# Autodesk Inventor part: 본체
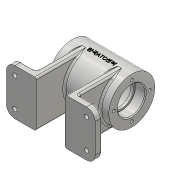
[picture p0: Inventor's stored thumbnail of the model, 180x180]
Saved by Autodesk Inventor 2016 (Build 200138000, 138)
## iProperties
Created: 2017-02
Part Number: 본체
Material: 알루미늄 6061
Document SubType Name: Modeling
Designer: H
Density: 2.7 g/cm^3
Appearance: 알루미늄 - 평지
Mass: 354.498 g
Surface Area: 423.593 cm^2
Volume: 131.296 cm^3
Author: H
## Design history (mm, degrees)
sketch "스케치1"
  geometry: L1 (0, 0)-(48.276, 0); L2 (0, 0)-(-37.135, 0); L3 (-35, 0)-(-35, 27); L4 (-35, 27)-(35, 27); L5 (35, 27)-(35, 0); L6 (0, 0)-(0, 35.697)
  constraints: 12 end point, 2 horizontal, 2 perpendicular, 2 point on line, 2 vertical
  dimensions: "d0" = 70 distance of L3.end L4.end; "d1" = 70 diameter of L3 L6; "d2" = 54 diameter of L4 L1
revolve "회전1" sketch "스케치1" stored, may be unused: angle "d3" = 90 deg
node "작업 평면1"
sketch "스케치2"
  geometry: L1 (35, 27)-(35, -27) reference; L2 (-35, 27)-(-35, -27) reference; L3 (0, 0)-(-50.692, 0); L4 (0, 0)-(76.762, 0); L5 (52, 27)-(-52, 27); L6 (-52, 27)-(-52, -27); L7 (-52, -27)-(52, -27); L8 (52, -27)-(52, 27); L9 (52, 27)-(-52, -27); L10 (-52, 27)-(52, -27)
  constraints: 16 end point, 3 horizontal, 2 midpoint, 2 parallel, 1 perpendicular
  dimensions: "d5" = 54 distance of L5.end L6.end; "d6" = 104 distance of L5.start L5.end
extrude "돌출1" join sketch "스케치2" distance "d7" = 8; taper "d8" = 0 deg
sketch "스케치3"
  geometry: L1 (0, 0)-(104, 0) reference; L2 (104, 0)-(104, 8) reference; L3 (0, 8)-(104, 8) reference; L4 (0, 0)-(0, 8) reference; L5 (52, 8)-(52, 0); L6 (69, 8)-(69, 0); L7 (35, 8)-(35, 0); L8 (35, 0)-(69, 0); L9 (35, 8)-(69, 8); 1 further point
  constraints: 10 end point, 2 midpoint, 2 perpendicular, 2 point on line, 2 symmetric about line, 1 collinear
  dimensions: "d9" = 17 distance from line of L6 L5.start
extrude "돌출2" cut sketch "스케치3" stored distance "d10" = 8; taper "d11" = 0 deg
sketch "스케치4"
  geometry: L1 (17, -27)-(17, 27) reference; L2 (52, 27)-(17, 27) reference; L3 (52, -27)-(52, 27) reference; L4 (17, -27)-(52, -27) reference; L5 (-17, 27)-(-17, -27) reference; L6 (-52, -27)-(-17, -27) reference; L7 (-52, 27)-(-52, -27) reference; L8 (-17, 27)-(-52, 27) reference; L9 (25, 27)-(25, -27); L10 (-25, 27)-(-25, -27); L11 (-25, 27)-(-17, 27); L12 (-17, 27)-(-17, -27); L13 (-17, -27)-(-25, -27); L14 (17, -27)-(25, -27); L15 (17, -27)-(17, 27); L16 (17, 27)-(25, 27); 1 further point
  constraints: 16 end point, 5 collinear, 4 point on line, 2 perpendicular, 1 vertical
  dimensions: "d12" = 8 distance between parallel lines of L9 L1; "d13" = 8 distance between parallel lines of L5 L10
extrude "돌출3" join sketch "스케치4" stored distance "d14" = 0; taper "d15" = 0 deg
fillet "모깎기1" dims "d16" = 10, "d17" = 10, "d18" = 10, "d19" = 10
sketch "스케치5"
  geometry: L1 (17, -27)-(42, -27) reference; L2 (17, -27)-(17, 27) reference; L3 (42, 27)-(17, 27) reference; L4 (52, -17)-(52, 17) reference; L5 (-17, 27)-(-42, 27) reference; L6 (-17, 27)-(-17, -27) reference; L7 (-42, -27)-(-17, -27) reference; L8 (-52, 17)-(-52, -17) reference; L9 (44.598, 21.5)-(47.196, 17); L10 (47.196, 17)-(44.598, 12.5); L11 (44.598, 12.5)-(39.402, 12.5); L12 (39.402, 12.5)-(36.804, 17); L13 (36.804, 17)-(39.402, 21.5); L14 (39.402, 21.5)-(44.598, 21.5); L15 (0, 0)-(12.572, 0); L16 (0, 0)-(0, 12.516); L17 (47.196, -17)-(44.598, -12.5); L18 (39.402, -12.5)-(36.804, -17); L19 (44.598, -21.5)-(47.196, -17); L20 (39.402, -21.5)-(44.598, -21.5); L21 (36.804, -17)-(39.402, -21.5); L22 (44.598, -12.5)-(39.402, -12.5); L23 (-44.598, -12.5)-(-39.402, -12.5); L24 (-39.402, -12.5)-(-36.804, -17); L25 (-47.196, -17)-(-44.598, -12.5); L26 (-36.804, -17)-(-39.402, -21.5); L27 (-39.402, -21.5)-(-44.598, -21.5); L28 (-44.598, -21.5)-(-47.196, -17); L29 (-36.804, 17)-(-39.402, 21.5); L30 (-39.402, 21.5)-(-44.598, 21.5); L31 (-44.598, 12.5)-(-39.402, 12.5); L32 (-44.598, 21.5)-(-47.196, 17); L33 (-47.196, 17)-(-44.598, 12.5); L34 (-39.402, 12.5)-(-36.804, 17); A1 r 10 centre (42, -17) between (42, -27) and (52, -17) reference; A2 r 10 centre (42, 17) between (52, 17) and (42, 27) reference; A3 r 10 centre (-42, 17) between (-42, 27) and (-52, 17) reference; A4 r 10 centre (-42, -17) between (-52, -17) and (-42, -27) reference; A5 r 10 centre (-42, 17) between (-42, 27) and (-52, 17); 11 further points
  constraints: 52 end point, 28 symmetric about line, 2 point on circle, 1 centre point, 1 horizontal, 1 midpoint, 1 vertical, 14 other
extrude "돌출4" cut sketch "스케치5" distance "d21" = 3; taper "d22" = 0 deg
sketch "스케치6"
  geometry: L1 (17, -27)-(42, -27) reference; L2 (17, -27)-(17, 27) reference; L3 (42, 27)-(17, 27) reference; L4 (52, -17)-(52, 17) reference; L5 (-17, 27)-(-42, 27) reference; L6 (-17, 27)-(-17, -27) reference; L7 (-42, -27)-(-17, -27) reference; L8 (-52, 17)-(-52, -17) reference; A1 r 10 centre (42, -17) between (42, -27) and (52, -17) reference; A2 r 10 centre (42, 17) between (52, 17) and (42, 27) reference; A3 r 10 centre (-42, 17) between (-42, 27) and (-52, 17) reference; A4 r 10 centre (-42, -17) between (-52, -17) and (-42, -27) reference; 5 further points
  constraints: 4 coincident
hole "구멍1" sketch "스케치6" at (-42, -17), (-42, 17), (42, 17), (42, -17) diameter "d23" = 5; stored, may be unused: countersink angle "d27" = 90 deg, drill point angle "d29" = 0 deg; dims "d24" = 6, "d25" = 4, "d26" = 2, "d28" = 8
sketch "스케치7"
  geometry: L1 (-35, -27)-(-35, 27) reference; L2 (-35, 27)-(35, 27) reference; L3 (35, -27)-(35, 27) reference; L4 (-35, -27)-(35, -27) reference; L5 (0, 0)-(22.79, 0); L6 (-35, 16)-(-23, 16); L7 (-23, 16)-(-23, 14); L8 (-23, 14)-(-20, 14); L9 (-20, 14)-(-20, 22); L10 (-20, 22)-(20, 22); L11 (20, 22)-(20, 14); L12 (20, 14)-(23, 14); L13 (23, 14)-(23, 16); L14 (23, 16)-(35, 16); L15 (-35, 16)-(-35, 0); L16 (35, 16)-(35, 0); L17 (-35, 0)-(35, 0)
  constraints: 26 end point, 7 perpendicular, 6 point on line, 2 horizontal, 2 midpoint
  dimensions: "d30" = 32 diameter of L14 L5; "d31" = 44 diameter of L10 L5; "d32" = 28 diameter of L12 L5; "d33" = 12 distance between parallel lines of L1 L7; "d34" = 40 distance between parallel lines of L11 L9; "d35" = 12 distance between parallel lines of L3 L13; "d36" = 3 distance of L11.end L12.end
revolve "회전2" sketch "스케치7" stored, may be unused: angle "d37" = 90 deg
sketch "스케치8"
  geometry: L1 (-35, 27)-(35, 27) reference; L2 (-35, -27)-(-35, 27) reference; L3 (-10, 27)-(-10, 42.717); L4 (-15, 27)-(-15, 32); L5 (-15, 32)-(-10, 32); L6 (-15, 27)-(-10, 27); 1 further point
  constraints: 8 end point, 3 point on line, 2 vertical, 1 collinear, 1 perpendicular
  dimensions: "d38" = 5 distance between parallel lines of L1 L5; "d39" = 25 distance from line of L2 L3.end; "d40" = 10 diameter of L4 L3
revolve "회전3" sketch "스케치8" stored, may be unused: angle "d41" = 90 deg
sketch "스케치9"
  geometry: C1 r 5 at (0, 0) reference; C2 r 5 at (0, 0); 1 further point
  constraints: 1 centre point, 1 coincident, 1 concentric
extrude "돌출5" join sketch "스케치9" stored distance "d42" = 3; taper "d43" = 0 deg
sketch "스케치10"
  geometry: L1 (0, 0)-(-32.149, 0); L2 (0, 0)-(-25.16, -16.339); C1 r 16 at (0, 0) reference; C2 r 27 at (0, 0) reference; 1 further point
  constraints: 4 end point, 1 horizontal
  dimensions: "d44" = 33 deg angle of L2 L1; "d45" = 30 distance of L1.start L2.end
  node "투영된 루프10"
node "작업 평면2"
sketch "스케치11"
  geometry: C1 r 6 at (0, 0); 1 further point
  constraints: 1 centre point, 1 coincident
  dimensions: "d46" = 12 diameter of C1
extrude "돌출6" join sketch "스케치11" stored distance "d47" = 0; taper "d48" = 0 deg
node "작업 평면3"
sketch "스케치12"
  geometry: L1 (-35, -27)-(-35, 27) reference; L2 (-35, 27)-(35, 27) reference; 2 further points
  constraints: 1 other
  dimensions: "d50" = 35 distance from line of point (0, 0) L1; "d51" = 27 distance from line of L2 point (0, 0)
feature "엠보싱1" sketch "스케치12" dims "d0" = 70, "d1" = 70, "d2" = 54, "d52" = 0.5, "d53" = 0
sketch "스케치13"
  geometry: C1 r 5 at (0, 0) reference; 2 further points
  constraints: 1 coincident
hole "구멍2" sketch "스케치13" at (0, 0) diameter "d54" = 5.188; stored, may be unused: countersink angle "d58" = 90 deg, drill point angle "d60" = 0 deg; dims "d55" = 30, "d56" = 4, "d57" = 2, "d59" = 16
sketch "스케치14"
  geometry: C1 r 6 at (0, 0) reference; 2 further points
  constraints: 1 coincident
hole "구멍3" sketch "스케치14" at (0, 0) diameter "d61" = 5.188; stored, may be unused: countersink angle "d65" = 90 deg, drill point angle "d67" = 0 deg; dims "d62" = 15, "d63" = 4, "d64" = 2, "d66" = 20
fillet "모깎기2" dims "d68" = 2
fillet "모깎기3" dims "d69" = 2
fillet "모깎기4" dims "d70" = 3
fillet "모깎기5" dims "d71" = 2
fillet "모깎기6" dims "d72" = 2
fillet "모깎기7" dims "d73" = 2
fillet "모깎기8" dims "d74" = 2
chamfer "모따기1" distance "d75" = 1; stored, may be unused: second distance "d76" = 2, angle "d77" = 45 deg
chamfer "모따기2" distance "d78" = 1; stored, may be unused: second distance "d79" = 2, angle "d80" = 45 deg
sketch "스케치15" dims "d81" = 42
  geometry: C1 r 27 at (0, 0) reference; C2 r 17 at (0, 0) reference; 3 further points
  constraints: 1 coincident, 1 vertical alignment, 2 other
hole "구멍4" sketch "스케치15" at (0, 21) diameter "d82" = 3.459; stored, may be unused: countersink angle "d86" = 90 deg, drill point angle "d88" = 118 deg; dims "d83" = 8, "d84" = 4, "d85" = 2, "d87" = 10
fillet "모깎기9" dims "d92" = 0.3, "d93" = 0.3
node "솔리드1"
pattern_circular "원형 패턴1" dims angle "d90" = 360 deg
mirror "대칭1"
node "투영된 루프1"
node "투영된 루프2"
node "투영된 루프3"
node "투영된 루프4"
node "투영된 루프5"
node "투영된 루프6"
node "투영된 루프7"
node "투영된 루프8"
node "투영된 루프9"
node "투영된 루프11"
node "투영된 루프12"
node "투영된 루프13"
other parameters: "d49" = 70.5
